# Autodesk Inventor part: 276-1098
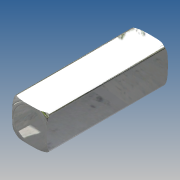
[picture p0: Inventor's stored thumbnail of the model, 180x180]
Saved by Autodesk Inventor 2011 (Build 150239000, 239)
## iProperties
Company: Autodesk Inc.
Created: 2010-06
Document SubType Name: Modeling
Designer: Autodesk Inc.
Density: 1 g/cm^3
Catalog Web Link: http://www.vexrobotics.com/276-1098.html
Vendor: Innovation First, Inc.
Part Number: 276-1098
Author: Autodesk Inc.
Title: VEX Robotics Kit of Parts
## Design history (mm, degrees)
sketch "Sketch1"
  geometry: L1 (0.378, 1.587)-(-0.378, 1.587); L2 (-1.334, 1.587)-(-0.378, 1.587); L3 (-1.588, 0.378)-(-1.588, -0.378); L4 (-0.378, -1.588)-(0.378, -1.588); L5 (-1.587, -1.334)-(-1.588, -0.378); L6 (-0.378, -1.588)-(-1.334, -1.587); L7 (-1.588, 0.378)-(-1.587, 1.334); L8 (1.587, 1.334)-(1.588, 0.378); L9 (0.378, 1.587)-(1.334, 1.587); L10 (1.588, -0.378)-(1.588, 0.378); L11 (1.334, -1.587)-(0.378, -1.588); L12 (1.588, -0.378)-(1.587, -1.334); A1 r 1.632 centre (0, 0) between (-0.378, 1.587) and (-1.588, 0.378); A2 r 1.632 centre (0, 0) between (-0.378, 1.587) and (-1.588, 0.378); A3 r 1.632 centre (0, 0) between (-1.588, -0.378) and (-0.378, -1.588); A4 r 1.632 centre (0, 0) between (-1.588, -0.378) and (-0.378, -1.588); A5 r 1.632 centre (0, 0) between (1.588, 0.378) and (0.378, 1.587); A6 r 1.632 centre (0, 0) between (1.588, 0.378) and (0.378, 1.587); A7 r 1.632 centre (0, 0) between (0.378, -1.588) and (1.588, -0.378); A8 r 1.632 centre (0, 0) between (0.378, -1.588) and (1.588, -0.378); 1 further point
  constraints: 24 end point, 16 point on circle, 8 centre point, 8 other
extrude "Extrusion1" new body sketch "Sketch1" distance "d0" = 11.1252; taper "d1" = 0 deg
workplane "Work Plane1"
  workaxis "Work Axis1"
sketch "Sketch2"
  geometry: L1 (0, 0)-(0.352, 0); L2 (0.352, 0)-(0.352, 2.14); L3 (0.352, 2.14)-(-0.254, 2.14); L4 (0, 0)-(0, 1.39); L5 (-13.421, 0)-(2.647, 0) reference; A1 r 0.772 centre (-0.757, 1.554) between (-0.179, 2.065) and (-0.254, 2.14); 1 further point
  constraints: 8 end point, 2 perpendicular, 2 point on circle, 1 centre point, 3 other
revolve "Revolution1" sketch "Sketch2" stored, may be unused: angle "d3" = 90 deg
workplane "Work Plane2"
mirror "Mirror1"
body "Solid1"
other parameters: "d2" = 90 deg
